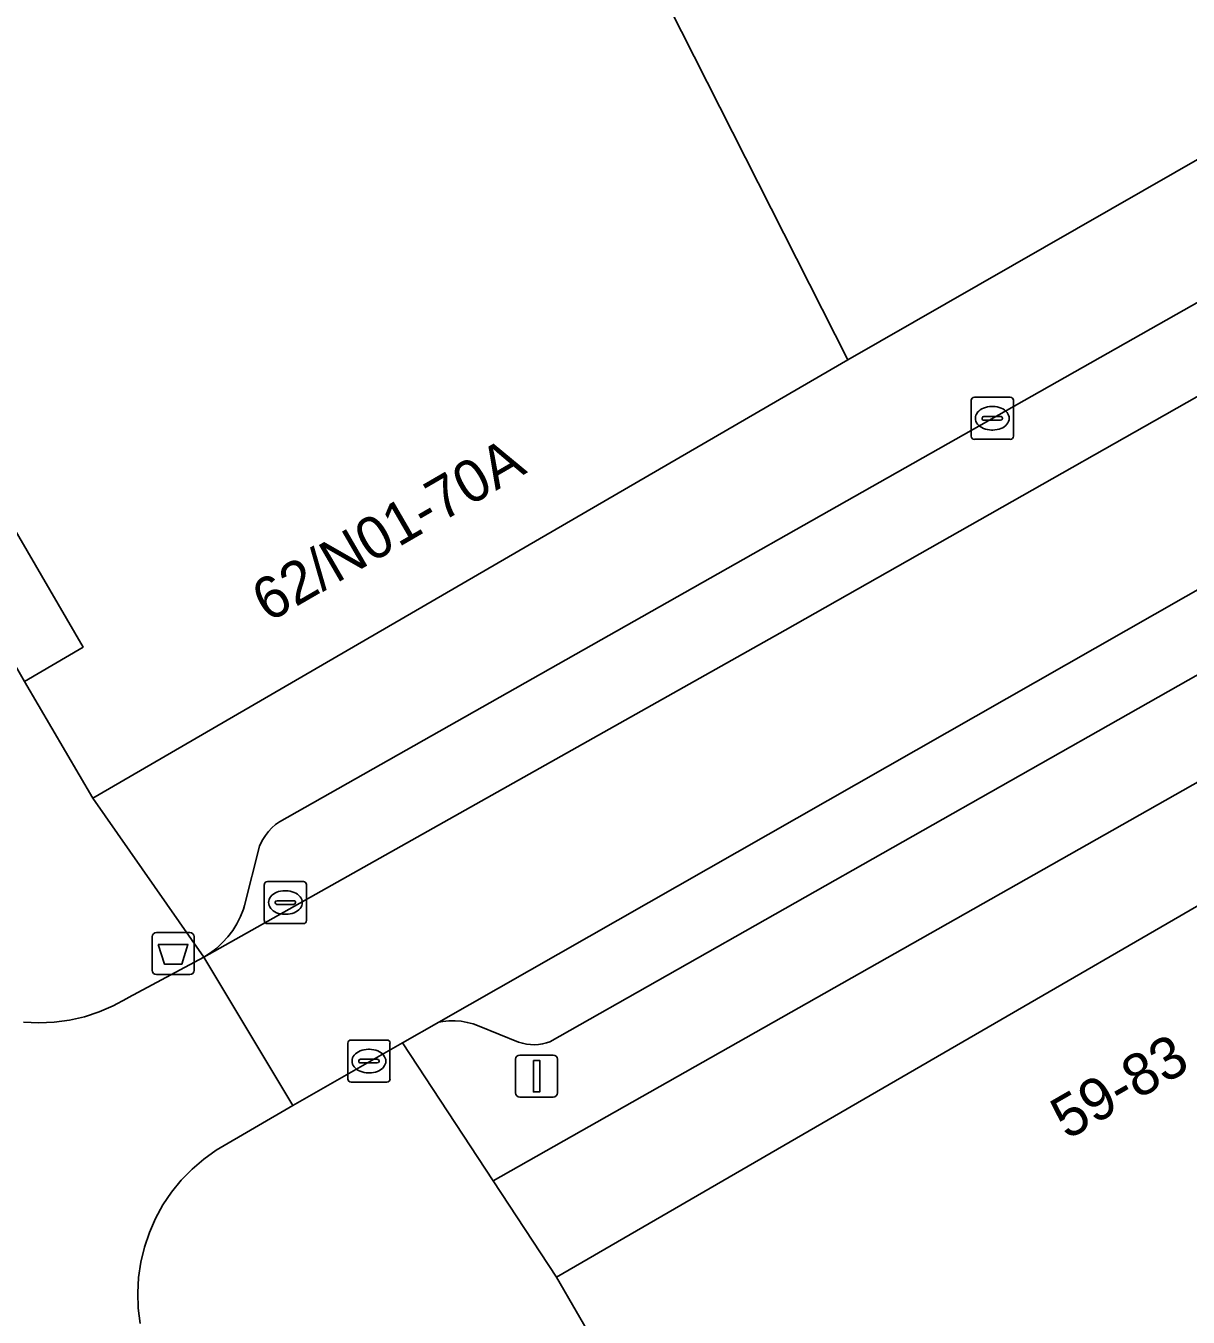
# Model space of a CAD drawing. Extents: x 160377 to 161131, y 383938 to 384853.
# Drawn here: x 160884.05 to 160911.65, y 384192.23 to 384222.89 of the extents above; entities that cross this region are included whole.
import ezdxf

# ---------------------------------------------------------------- set-up
doc = ezdxf.new("R2010")
doc.units = 0
for name, color, linetype in [('IMGEO_Afvalbak', 7, 'Continuous'), ('IMGEO_Erf', 7, 'Continuous'), ('IMGEO_Groenvoorziening', 7, 'Continuous'), ('IMGEO_Kolk', 7, 'Continuous'), ('IMGEO_Lichtmast', 7, 'Continuous'), ('IMGEO_Pand', 7, 'Continuous'), ('IMGEO_Pand_nummerreeks', 7, 'Continuous'), ('IMGEO_Pand_overbouw', 7, 'Continuous'), ('IMGEO_Parkeervlak_open', 7, 'Continuous'), ('IMGEO_Rijbaan_lokaal_open', 7, 'Continuous'), ('IMGEO_Voetpad_open', 7, 'Continuous')]:
    doc.layers.add(name, color=color, linetype=linetype)

msp = doc.modelspace()

# ---------------------------------------------------------------- linework, layer by layer
at = {"layer": 'IMGEO_Afvalbak'}
for p, q in [((160887.153, 384201.365), (160887.943, 384201.365)), ((160887.943, 384201.365), (160887.153, 384201.365)), ((160887.053, 384200.465), (160887.053, 384201.265)), ((160887.053, 384201.265), (160887.053, 384200.465)), ((160888.043, 384201.265), (160888.043, 384200.465)), ((160888.043, 384200.465), (160888.043, 384201.265)), ((160887.943, 384200.365), (160887.153, 384200.365)), ((160887.153, 384200.365), (160887.943, 384200.365))]:
    msp.add_line(p, q, dxfattribs=at)
msp.add_lwpolyline([(160887.196, 384201.079), (160887.9, 384201.079), (160887.751, 384200.609), (160887.345, 384200.609), (160887.196, 384201.079)], dxfattribs=at)
for centre, start, end in [((160887.153, 384201.265), 90, 180), ((160887.153, 384201.265), 90, 180), ((160887.943, 384201.265), 0, 90), ((160887.943, 384201.265), 360, 90), ((160887.153, 384200.465), 180, 270), ((160887.153, 384200.465), 180, 270), ((160887.943, 384200.465), 270, 0), ((160887.943, 384200.465), 270, 0)]:
    msp.add_arc(centre, 0.1, start, end, dxfattribs=at)
at = {"layer": 'IMGEO_Erf'}
msp.add_lwpolyline([(160899.008, 384223.96), (160903.567, 384214.961), (160912.905, 384220.302), (160921.193, 384223.735)], dxfattribs=at)
at = {"layer": 'IMGEO_Groenvoorziening'}
msp.add_lwpolyline([(160895.144, 384195.469), (160896.65, 384193.18), (160922.401, 384208.091), (160922.968, 384206.736), (160925.158, 384207.624), (160924.182, 384209.958), (160923.82, 384210.826), (160918.722, 384208.725), (160916.92, 384207.792)], close=True, dxfattribs=at)
at = {"layer": 'IMGEO_Kolk'}
for p, q in [((160906.498, 384213.144), (160906.498, 384213.996)), ((160906.573, 384214.07), (160907.425, 384214.07)), ((160907.499, 384213.996), (160907.499, 384213.144)), ((160906.8, 384213.613), (160907.198, 384213.613)), ((160906.986, 384213.85), (160907.011, 384213.85)), ((160906.757, 384213.564), (160906.757, 384213.576)), ((160907.195, 384213.527), (160906.797, 384213.527)), ((160907.009, 384213.29), (160906.984, 384213.29)), ((160907.241, 384213.576), (160907.241, 384213.564)), ((160907.425, 384213.07), (160906.573, 384213.07)), ((160889.788, 384202.575), (160890.64, 384202.575)), ((160889.713, 384201.649), (160889.713, 384202.501)), ((160890.201, 384202.355), (160890.226, 384202.355)), ((160890.714, 384202.501), (160890.714, 384201.649)), ((160889.972, 384202.069), (160889.972, 384202.081)), ((160890.41, 384202.032), (160890.012, 384202.032)), ((160890.015, 384202.118), (160890.413, 384202.118)), ((160890.456, 384202.081), (160890.456, 384202.069)), ((160890.224, 384201.795), (160890.199, 384201.795)), ((160890.64, 384201.575), (160889.788, 384201.575)), ((160891.696, 384197.885), (160891.696, 384198.737)), ((160891.771, 384198.811), (160892.623, 384198.811)), ((160892.184, 384198.591), (160892.209, 384198.591)), ((160892.697, 384198.737), (160892.697, 384197.885)), ((160891.955, 384198.305), (160891.955, 384198.317)), ((160892.393, 384198.268), (160891.995, 384198.268)), ((160891.998, 384198.354), (160892.396, 384198.354)), ((160892.439, 384198.317), (160892.439, 384198.305)), ((160892.207, 384198.031), (160892.182, 384198.031)), ((160892.623, 384197.811), (160891.771, 384197.811))]:
    msp.add_line(p, q, dxfattribs=at)
for points in [[(160906.498, 384213.144), (160906.498, 384213.996)], [(160906.573, 384214.07), (160907.425, 384214.07)], [(160907.499, 384213.996), (160907.499, 384213.144)], [(160907.425, 384213.07), (160906.573, 384213.07)], [(160889.788, 384202.575), (160890.64, 384202.575)], [(160889.713, 384201.649), (160889.713, 384202.501)], [(160890.714, 384202.501), (160890.714, 384201.649)], [(160890.64, 384201.575), (160889.788, 384201.575)], [(160891.696, 384197.885), (160891.696, 384198.737)], [(160891.771, 384198.811), (160892.623, 384198.811)], [(160892.697, 384198.737), (160892.697, 384197.885)], [(160892.623, 384197.811), (160891.771, 384197.811)]]:
    msp.add_lwpolyline(points, dxfattribs=at)
for centre, radius, start, end in [((160906.575, 384213.994), 0.0765, 91.552, 178.448), ((160906.575, 384213.994), 0.0765, 91.552, 178.448), ((160907.423, 384213.994), 0.0765, 1.552, 88.448), ((160907.423, 384213.994), 0.0765, 1.552, 88.448), ((160906.797, 384213.573), 0.0403, 85.8775, 175.7526), ((160907.202, 384213.575), 0.0386, 1.7309, 96.639), ((160906.794, 384213.563), 0.0366, 178.938, 274.7102), ((160907.198, 384213.57), 0.043, 264.8664, 352.4533), ((160906.575, 384213.146), 0.0765, 181.552, 268.448), ((160906.575, 384213.146), 0.0765, 181.552, 268.448), ((160907.423, 384213.146), 0.0765, 271.552, 358.448), ((160907.423, 384213.146), 0.0765, 271.552, 358.448), ((160889.79, 384202.499), 0.0765, 91.552, 178.448), ((160889.79, 384202.499), 0.0765, 91.552, 178.448), ((160890.638, 384202.499), 0.0765, 1.552, 88.448), ((160890.638, 384202.499), 0.0765, 1.552, 88.448), ((160890.012, 384202.078), 0.0403, 85.8775, 175.7526), ((160890.009, 384202.068), 0.0366, 178.938, 274.7102), ((160890.413, 384202.075), 0.043, 264.8664, 352.4533), ((160890.417, 384202.08), 0.0386, 1.7309, 96.639), ((160889.79, 384201.651), 0.0765, 181.552, 268.448), ((160889.79, 384201.651), 0.0765, 181.552, 268.448), ((160890.638, 384201.651), 0.0765, 271.552, 358.448), ((160890.638, 384201.651), 0.0765, 271.552, 358.448), ((160891.773, 384198.735), 0.0765, 91.552, 178.448), ((160891.773, 384198.735), 0.0765, 91.552, 178.448), ((160892.621, 384198.735), 0.0765, 1.552, 88.448), ((160892.621, 384198.735), 0.0765, 1.552, 88.448), ((160891.995, 384198.314), 0.0403, 85.8775, 175.7526), ((160891.992, 384198.304), 0.0366, 178.938, 274.7102), ((160892.396, 384198.311), 0.043, 264.8664, 352.4533), ((160892.4, 384198.316), 0.0386, 1.7309, 96.639), ((160891.773, 384197.887), 0.0765, 181.552, 268.448), ((160891.773, 384197.887), 0.0765, 181.552, 268.448), ((160892.621, 384197.887), 0.0765, 271.552, 358.448), ((160892.621, 384197.887), 0.0765, 271.552, 358.448)]:
    msp.add_arc(centre, radius, start, end, dxfattribs=at)
for centre, major_axis, ratio, start_param, end_param in [((160906.985, 384213.57), (-0.387, 0.002), 0.722429, 4.712389, 7.853982), ((160907.01, 384213.57), (-0.39, 0.002), 0.717154, 1.570796, 4.712389), ((160890.2, 384202.075), (-0.387, 0.002), 0.722429, 4.712389, 7.853982), ((160890.225, 384202.075), (-0.39, 0.002), 0.717154, 1.570796, 4.712389), ((160892.183, 384198.311), (-0.387, 0.002), 0.722429, 4.712389, 7.853982), ((160892.208, 384198.311), (-0.39, 0.002), 0.717154, 1.570796, 4.712389)]:
    msp.add_ellipse(centre, major_axis=major_axis, ratio=ratio, start_param=start_param, end_param=end_param, dxfattribs=at)
at = {"layer": 'IMGEO_Lichtmast'}
for p, q in [((160895.681, 384197.554), (160895.681, 384198.354)), ((160895.681, 384198.354), (160895.681, 384197.554)), ((160895.781, 384198.454), (160896.571, 384198.454)), ((160896.571, 384198.454), (160895.781, 384198.454)), ((160896.671, 384198.354), (160896.671, 384197.554)), ((160896.671, 384197.554), (160896.671, 384198.354)), ((160896.571, 384197.454), (160895.781, 384197.454)), ((160895.781, 384197.454), (160896.571, 384197.454))]:
    msp.add_line(p, q, dxfattribs=at)
msp.add_lwpolyline([(160896.101, 384198.329), (160896.251, 384198.329), (160896.251, 384197.579), (160896.101, 384197.579), (160896.101, 384198.329)], dxfattribs=at)
for centre, start, end in [((160895.781, 384198.354), 90, 180), ((160895.781, 384198.354), 90, 180), ((160896.571, 384198.354), 0, 90), ((160896.571, 384198.354), 360, 90), ((160895.781, 384197.554), 180, 270), ((160895.781, 384197.554), 180, 270), ((160896.571, 384197.554), 270, 0), ((160896.571, 384197.554), 270, 0)]:
    msp.add_arc(centre, 0.1, start, end, dxfattribs=at)
at = {"layer": 'IMGEO_Pand'}
for points in [[(160899.008, 384223.96), (160891.632, 384239.808), (160882.946, 384236.033), (160878.215, 384233.977), (160870.628, 384230.556), (160872.611, 384226.95), (160874.008, 384227.747), (160885.41, 384208.137), (160884.021, 384207.323), (160885.643, 384204.556), (160903.567, 384214.961)], [(160916.797, 384195.689), (160916.149, 384196.809), (160924.66, 384201.737), (160927.372, 384195.459), (160930.736, 384197.407), (160928.502, 384202.578), (160928.224, 384204.957), (160926.872, 384208.321), (160925.158, 384207.624), (160922.968, 384206.736), (160922.401, 384208.091), (160896.65, 384193.18), (160903.19, 384181.885), (160910.211, 384185.937), (160914.824, 384188.599), (160912.246, 384193.053)]]:
    msp.add_lwpolyline(points, close=True, dxfattribs=at)
at = {"layer": 'IMGEO_Pand_overbouw'}
msp.add_lwpolyline([(160874.008, 384227.747), (160872.611, 384226.95), (160873.258, 384225.823), (160873.588, 384225.269), (160874.241, 384224.122), (160874.571, 384223.567), (160875.212, 384222.444), (160875.542, 384221.89), (160876.192, 384220.76), (160876.522, 384220.206), (160877.165, 384219.097), (160877.987, 384217.683), (160878.638, 384216.558), (160878.968, 384216.004), (160879.61, 384214.875), (160879.94, 384214.321), (160880.581, 384213.218), (160881.403, 384211.804), (160882.049, 384210.687), (160882.379, 384210.132), (160883.034, 384209.009), (160883.364, 384208.455), (160884.021, 384207.323), (160885.41, 384208.137)], close=True, dxfattribs=at)
at = {"layer": 'IMGEO_Parkeervlak_open'}
for points in [[(160913.35, 384217.154), (160890.076, 384203.994), (160889.981, 384203.924), (160889.893, 384203.846), (160889.812, 384203.761), (160889.74, 384203.669), (160889.675, 384203.57), (160889.62, 384203.466), (160889.595, 384203.41), (160889.246, 384202.005), (160889.218, 384201.917), (160889.148, 384201.742), (160889.063, 384201.573), (160888.963, 384201.413), (160888.85, 384201.263), (160888.723, 384201.123), (160888.584, 384200.995), (160888.435, 384200.879), (160888.276, 384200.778), (160902.078, 384208.542), (160916.242, 384216.564)], [(160915.841, 384211.763), (160893.856, 384199.235), (160893.949, 384199.251), (160894.094, 384199.265), (160894.241, 384199.266), (160894.387, 384199.255), (160894.532, 384199.23), (160894.673, 384199.192), (160894.811, 384199.142), (160895.748, 384198.761), (160895.841, 384198.733), (160895.936, 384198.713), (160896.032, 384198.702), (160896.129, 384198.699), (160896.226, 384198.705), (160896.322, 384198.72), (160896.416, 384198.743), (160896.493, 384198.769), (160916.047, 384209.846)]]:
    msp.add_lwpolyline(points, dxfattribs=at)
at = {"layer": 'IMGEO_Rijbaan_lokaal_open'}
for points in [[(160916.242, 384216.564), (160902.078, 384208.542), (160888.276, 384200.778), (160890.389, 384197.259), (160892.991, 384198.742), (160893.856, 384199.235), (160915.841, 384211.763)], [(160886.765, 384192.084), (160886.72, 384192.447), (160886.708, 384192.812), (160886.728, 384193.177), (160886.781, 384193.539), (160886.867, 384193.895), (160886.983, 384194.242), (160887.13, 384194.576), (160887.306, 384194.897), (160887.511, 384195.2), (160887.741, 384195.484), (160887.996, 384195.746), (160888.274, 384195.984), (160888.571, 384196.197), (160890.389, 384197.259), (160888.276, 384200.778), (160886.486, 384199.819), (160886.446, 384199.794), (160886.125, 384199.621), (160885.789, 384199.478), (160885.443, 384199.365), (160885.087, 384199.283), (160884.726, 384199.233), (160884.362, 384199.216), (160883.998, 384199.232)]]:
    msp.add_lwpolyline(points, dxfattribs=at)
at = {"layer": 'IMGEO_Voetpad_open'}
for points in [[(160884.021, 384207.323), (160885.41, 384208.137), (160874.008, 384227.747)], [(160912.905, 384220.302), (160903.567, 384214.961), (160885.643, 384204.556), (160888.276, 384200.778), (160888.435, 384200.879), (160888.584, 384200.995), (160888.723, 384201.123), (160888.85, 384201.263), (160888.963, 384201.413), (160889.063, 384201.573), (160889.148, 384201.742), (160889.218, 384201.917), (160889.246, 384202.005), (160889.595, 384203.41), (160889.62, 384203.466), (160889.675, 384203.57), (160889.74, 384203.669), (160889.812, 384203.761), (160889.893, 384203.846), (160889.981, 384203.924), (160890.076, 384203.994), (160913.35, 384217.154)], [(160916.047, 384209.846), (160896.493, 384198.769), (160896.416, 384198.743), (160896.322, 384198.72), (160896.226, 384198.705), (160896.129, 384198.699), (160896.032, 384198.702), (160895.936, 384198.713), (160895.841, 384198.733), (160895.748, 384198.761), (160894.811, 384199.142), (160894.673, 384199.192), (160894.532, 384199.23), (160894.387, 384199.255), (160894.241, 384199.266), (160894.094, 384199.265), (160893.949, 384199.251), (160893.856, 384199.235), (160892.991, 384198.742), (160895.144, 384195.469), (160916.92, 384207.792)], [(160883.998, 384199.232), (160884.362, 384199.216), (160884.726, 384199.233), (160885.087, 384199.283), (160885.443, 384199.365), (160885.789, 384199.478), (160886.125, 384199.621), (160886.446, 384199.794), (160886.486, 384199.819), (160888.276, 384200.778), (160885.643, 384204.556), (160884.021, 384207.323)], [(160903.19, 384181.885), (160896.65, 384193.18), (160895.144, 384195.469), (160892.991, 384198.742), (160890.389, 384197.259), (160888.571, 384196.197), (160888.274, 384195.984), (160887.996, 384195.746), (160887.741, 384195.484), (160887.511, 384195.2), (160887.306, 384194.897), (160887.13, 384194.576), (160886.983, 384194.242), (160886.867, 384193.895), (160886.781, 384193.539), (160886.728, 384193.177), (160886.708, 384192.812), (160886.72, 384192.447), (160886.765, 384192.084)]]:
    msp.add_lwpolyline(points, dxfattribs=at)

# ---------------------------------------------------------------- texts
at = {"layer": 'IMGEO_Pand_nummerreeks'}
for s, rotation, p in [('62/N01-70A', 30.1376, (160889.808, 384208.708)), ('59-83', 29.9027, (160908.775, 384196.429))]:
    msp.add_text(s, height=1, rotation=rotation, dxfattribs=at).set_placement(p)

doc.saveas('drawing.dxf')
